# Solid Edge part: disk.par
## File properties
Author: Binay
Template: sync ansi part.par
Last saved by: Cadcim
Revision: 2
Application: Solid Edge
Accuracy: 0.990
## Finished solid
Body 1: solid body, 19 faces, 50 edges, 32 vertices.
  Faces by surface: plane 10, cylinder 9
  Edges by curve: line 32, circle 18
Bounding box of the edges (mm): 50.402 x 50.402 x 3.175, from (2.9188, 47.4242, -1.5875) to (53.3204, 97.8258, 1.5875).
Cylindrical faces by radius (mm): R3.175 x4, R12.7 x1, R25.4 x4
Planar faces by outward normal: +x 2, +y 2, +z 1, -x 2, -y 2, -z 1
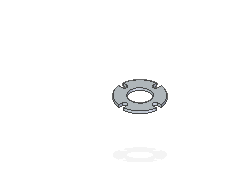
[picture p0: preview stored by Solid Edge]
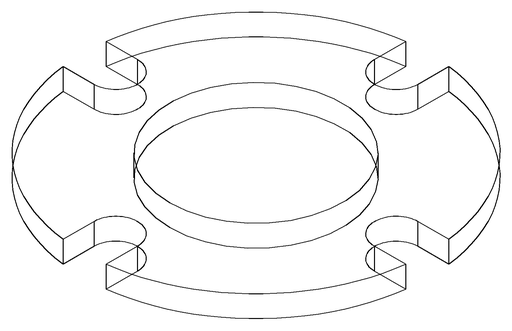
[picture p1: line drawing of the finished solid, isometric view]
